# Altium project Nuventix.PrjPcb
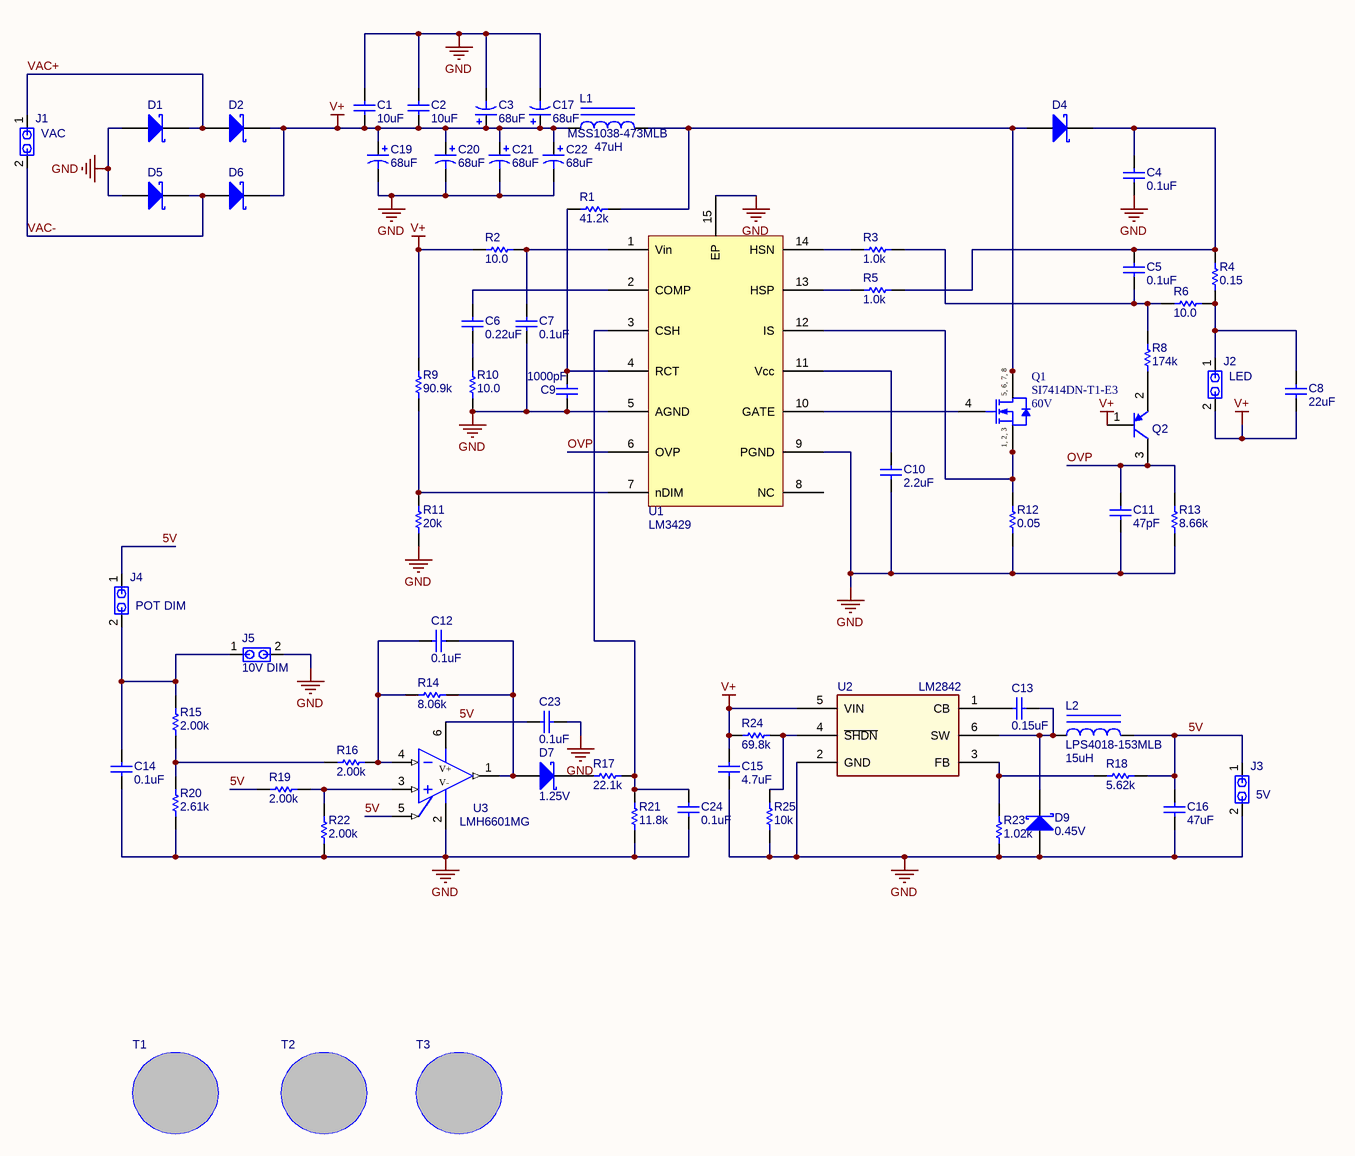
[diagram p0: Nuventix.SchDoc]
TechSupport: http://www.national.com/support; SCH_Rev: X1; PRJ_Title: Nuventix; PRJ_Customer: Public Release; PRJ_BasePN: xxxxxx; PCB_MinorRev: -001
1 sheet, 69 parts. Net scope: global (net labels, ports and power ports of the same name join across sheets).
Board file: Nuventix.PcbDoc

## Sheet Nuventix.SchDoc: LM3429 Nuventix Design
size B; Date: Not shown in title block; ApprovedBy: Not shown in title block; CheckedBy: Not shown in title block; Author: Not shown in title block; CompanyName: Not shown in title block; DrawnBy: Not shown in title block; Engineer: Not shown in title block; Organization: Not shown in title block; Address1: Not shown in title block; Address2: Not shown in title block; Address3: Not shown in title block; Address4: Not shown in title block; DocumentNumber: 1; Revision: Use project parameter SCH_Rev; SheetNumber: 1; SheetTotal: 1; PageSetup: Record=PageOptions|CenterHorizontal=True|CenterVertical=True|PrintScale=1.00|XCorrection=1.00|YCorrection=1.00|PrintKind=0|BorderSize=5000000|LeftOffset=0|BottomOffset=0|Orientation=2|PaperLength=1000|PaperWidth=1000|Scale=100|PaperSource=15|PrintQuality=600|MediaType=1|DitherType=10|PaperKind=Letter|PrintScaleMode=0

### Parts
C1  value 10uF  [2220]  (hidden comment: C5750X7R1H106M)
C2  value 10uF  [2220]  (hidden comment: C5750X7R1H106M)
C3  value 68uF  [7361-38]  (hidden comment: TPSV686M025R0095)
C4  value 0.1uF  [0805]  (hidden comment: 08053C104KAT2A)
C5  value 0.1uF  [0805]  (hidden comment: 08053C104KAT2A)
C6  value 0.22uF  [0603]  (hidden comment: 06033D224KAT2A)
C7  value 0.1uF  [0805]  (hidden comment: 08053C104KAT2A)
C8  value 22uF  [1210]  (hidden comment: GRM32ER61E226KE15L)
C9  value 1000pF  [0603]  (hidden comment: 06031C102JAT2A)
C10  value 2.2uF  [0805]  (hidden comment: 0805ZD225KAT2A)
C11  value 47pF  [0603]  (hidden comment: 06035A470JAT2A)
C12  value 0.1uF  [0805]  (hidden comment: GRM219R71C104KA01D)
C13  value 0.15uF  [0805]  (hidden comment: 08053C154KAT2A)
C14  value 0.1uF  [0805]  (hidden comment: GRM219R71C104KA01D)
C15  value 4.7uF  [1210]  (hidden comment: GRM32ER71H475KA88L)
C16  value 47uF  [0805]  (hidden comment: JMK212BJ476MG-T)
C17  value 68uF  [7361-38]  (hidden comment: TPSV686M025R0095)
C19  value 68uF  [7361-38]  (hidden comment: TPSV686M025R0095)
C20  value 68uF  [7361-38]  (hidden comment: TPSV686M025R0095)
C21  value 68uF  [7361-38]  (hidden comment: TPSV686M025R0095)
C22  value 68uF  [7361-38]  (hidden comment: TPSV686M025R0095)
C23  value 0.1uF  [0603]  (hidden comment: 0603YC104JAT2A)
C24  value 0.1uF  [0603]  (hidden comment: 0603YC104JAT2A)
D1  MBRA160T3G  [SMA]  (value not drawn)
D2  MBRA160T3G  [SMA]  (value not drawn)
D4  MBRA160T3G  [SMA]  (value not drawn)
D5  MBRA160T3G  [SMA]  (value not drawn)
D6  MBRA160T3G  [SMA]  (value not drawn)
D7  value 1.25V  [SOD-123]  (hidden comment: 1N4148W-7-F)
D9  value 0.45V  [SOD-123]  (hidden comment: 1N5819HW-7-F)
J1  VAC  [0.1" header 2-pos]
J2  LED  [0.1" header 2-pos]
J3  5V  [0.1" header 2-pos]
J4  POT DIM  [0.1" header 2-pos]
J5  10V DIM  [0.1" header 2-pos]
L1  value 47uH  [MSS1038]  (hidden comment: MSS1038-473MLB)
L2  LPS4018-153MLB  value 15uH  [LPS4018]
Q1  SI7414DN-T1-E3  value 60V  [1212-8 Powerpack_smask]
Q2  CMPT3906 LEAD FREE  [SOT-23]  (value not drawn)
R1  value 41.2k  [0603]  (hidden comment: CRCW060341k2FKEA)
R2  value 10.0  [0603]  (hidden comment: CRCW060310R0FKEA)
R3  value 1.0k  [0603]  (hidden comment: CRCW06031k00JNEA)
R4  value 0.15  [1206]  (hidden comment: ERJ-8RSJR15V)
R5  value 1.0k  [0603]  (hidden comment: CRCW06031k00JNEA)
R6  value 10.0  [0603]  (hidden comment: CRCW060310R0FKEA)
R8  value 174k  [0603]  (hidden comment: RT0603BRD07174KL)
R9  value 90.9k  [0603]  (hidden comment: CRCW060390k9FKEA)
R10  value 10.0  [0603]  (hidden comment: CRCW060310R0FKEA)
R11  value 20k  [0603]  (hidden comment: CRCW060320k0JNEA)
R12  value 0.05  [1206]  (hidden comment: LVK12R050FER)
R13  value 8.66k  [0603]  (hidden comment: CRCW06038k66FKEA)
R14  value 8.06k  [0603]  (hidden comment: CRCW06038k06FKEA)
R15  value 2.00k  [0603]  (hidden comment: CRCW06032k00FKEA)
R16  value 2.00k  [0603]  (hidden comment: CRCW06032k00FKEA)
R17  value 22.1k  [0603]  (hidden comment: CRCW060322k1FKEA)
R18  value 5.62k  [0603]  (hidden comment: CRCW06035k62FKEA)
R19  value 2.00k  [0603]  (hidden comment: CRCW06032k00FKEA)
R20  value 2.61k  [0603]  (hidden comment: CRCW06032k61FKEA)
R21  value 11.8k  [0603]  (hidden comment: CRCW060311k8FKEA)
R22  value 2.00k  [0603]  (hidden comment: CRCW06032k00FKEA)
R23  value 1.02k  [0603]  (hidden comment: CRCW06031k02FKEA)
R24  value 69.8k  [0603]  (hidden comment: CRCW060369k8FKEA)
R25  value 10k  [0603]  (hidden comment: CRCW060310k0JNEA)
T1  TOOLING HOLE  [4-40 Mounting Hole]  (value not drawn)  (no BOM)
T2  TOOLING HOLE  [4-40 Mounting Hole]  (value not drawn)  (no BOM)
T3  TOOLING HOLE  [4-40 Mounting Hole]  (value not drawn)  (no BOM)
U1  LM3429  [TSSOP-14_EP]
U2  LM2842  [MK06A]
U3  LMH6601MG  [MAA06A]

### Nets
GND: C1.2 C2.2 C3.2(-) C4.2 C7.2 C9.2 C10.2 C11.2 C14.2 C15.2 C16.2 C17.2(-) C19.2(-) C20.2(-) C21.2(-) C22.2(-) C23.2 C24.1 D1.1(A) D5.1(A) D9.1(A) J3.2 J5.2 R10.2 R11.2 R12.2 R13.2 R20.2 R21.2 R22.2 R23.1 R25.2 U1.5(AGND) U1.9(PGND) U1.15(EP) U2.2(GND) U3.2(V-)
V+: C1.1 C2.1 C3.1(+) C8.2 C15.1 C17.1(+) C19.1(+) C20.1(+) C21.1(+) C22.1(+) D2.2(K) D6.2(K) J2.2 L1.1 Q2.1(B) R2.2 R9.1 R24.2 U2.5(VIN)
5V: C16.1 C23.1 J3.1 J4.1 L2.2 R18.1 R19.2 U3.5(SD) U3.6(V+)
OVP: C11.1 Q2.3(C) R13.1 U1.6(OVP)
VAC+: D1.2(K) D2.1(A) J1.1
VAC-: D5.2(K) D6.1(A) J1.2
NetC4_1: C4.1 C5.1 D4.2(K) R4.1 R5.1
NetC5_2: C5.2 R3.1 R6.1 R8.1
NetC6_1: C6.1 U1.2(COMP)
NetC6_2: C6.2 R10.1
NetC7_1: C7.1 R2.1 U1.1(Vin)
NetC8_1: C8.1 J2.1 R4.2 R6.2
NetC9_1: C9.1 R1.1 U1.4(RCT)
NetC10_1: C10.1 U1.11(Vcc)
NetC12_1: C12.1 D7.1(A) R14.1 U3.1(OUT)
NetC12_2: C12.2 R14.2 R16.1 U3.4(IN-)
NetC13_1: C13.1 D9.2(K) L2.1 U2.6(SW)
NetC13_2: C13.2 U2.1(CB)
NetC14_1: C14.1 J4.2 J5.1 R15.1
NetC24_2: C24.2 R17.1 R21.1 U1.3(CSH)
NetD4_1: D4.1(A) L1.2 Q1.5(D) Q1.6(D) Q1.7(D) Q1.8(D) Q1.9(D) R1.2
NetD7_2: D7.2(K) R17.2
NetQ1_1: Q1.1(S) Q1.2(S) Q1.3(S) R12.1 U1.12(IS)
NetQ1_4: Q1.4(G) U1.10(GATE)
NetQ2_2: Q2.2(E) R8.2
NetR3_2: R3.2 U1.14(HSN)
NetR5_2: R5.2 U1.13(HSP)
NetR9_2: R9.2 R11.1 U1.7(nDIM)
NetR15_2: R15.2 R16.2 R20.1
NetR18_2: R18.2 R23.2 U2.3(FB)
NetR19_1: R19.1 R22.1 U3.3(IN+)
NetR24_1: R24.1 R25.1 U2.4(~{SHDN})

Not connected (* = marked no-connect by the designer): U1 8(NC)

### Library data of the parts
C1 C2 = C5750X7R1H106M: Ceramic, X7R, 50V, 20%; Manufacturer: TDK; ESR_Ohm: 0.003; IRMS_A: 5.5; Polarized: N; TaMax_C: 125; TaMin_C: -55; Tolerance_%: 20; VDC_V: 50; CompType: Capacitor; Cap_F: 10.0E-6; Value1: 0.003 Ohm
C3 C17 C19-C21 = TPSV686M025R0095: TA, 25V, 20%, 0.095 Ohm ESR; Manufacturer: AVX; Cap_Case: V; ESR_Ohm: 0.095; IRMS_A: 1.46; Polarized: Y; TaMax_C: 125; TaMin_C: -55; Tolerance_%: 20; VDC_V: 25; CompType: Capacitor; Cap_F: 68.0E-6; Dielectric: TPS
C4 C5 C7 = 08053C104KAT2A: Ceramic, X7R, 25V, 10%; Manufacturer: AVX; ESR_Ohm: 0.28; Polarized: N; TaMax_C: 125; TaMin_C: -55; Tolerance_%: 10; VDC_V: 25; Cap_F: 100.0E-9; CompType: Capacitor; Value1: 0.28 Ohm
C6 = 06033D224KAT2A: Ceramic, X5R, 25V, 10%; Manufacturer: AVX; ESR_Ohm: 0.036; Polarized: N; TaMax_C: 85; TaMin_C: -55; Tolerance_%: 10; VDC_V: 25; Cap_F: 220.0E-9; CompType: Capacitor; Value1: 0.036 Ohm
C8 = GRM32ER61E226KE15L: Ceramic, X5R, 25V, 10%; Manufacturer: MuRata; ESR_Ohm: 0.002; Polarized: N; TaMax_C: 85; TaMin_C: -55; Tolerance_%: 10; VDC_V: 25; Cap_F: 22.0E-6; CompType: Capacitor; Value1: 0.002 Ohm
C9 = 06031C102JAT2A: Ceramic, X7R, 100V, 5%; Manufacturer: AVX; ESR_Ohm: 0.276; Polarized: N; TaMax_C: 125; TaMin_C: -55; Tolerance_%: 5; VDC_V: 100; Cap_F: 1.0E-9; CompType: Capacitor; Value1: 0.276 Ohm
C10 = 0805ZD225KAT2A: Ceramic, X5R, 10V, 10%; Manufacturer: AVX; ESR_Ohm: 0.009; Polarized: N; TaMax_C: 85; TaMin_C: -55; Tolerance_%: 10; Cap_F: 2.2E-6; CompType: Capacitor; Value1: 0.009 Ohm
C11 = 06035A470JAT2A: Ceramic, C0G/NP0, 50V, 5%; Manufacturer: AVX; ESR_Ohm: 0.174; Polarized: N; TaMax_C: 125; TaMin_C: -55; Tolerance_%: 5; VDC_V: 50; Cap_F: 47.0E-12; CompType: Capacitor; Value1: 0.174 Ohm
C12 C14 = GRM219R71C104KA01D: Ceramic, X7R, 16V, 10%; Manufacturer: MuRata; Polarized: N; TaMax_C: 125; TaMin_C: -55; Tolerance_%: 10; VDC_V: 16; Cap_F: 100.0E-9; CompType: Capacitor
C13 = 08053C154KAT2A: Ceramic, X7R, 25V, 10%; Manufacturer: AVX; ESR_Ohm: 0.02; Polarized: N; TaMax_C: 125; TaMin_C: -55; Tolerance_%: 10; VDC_V: 25; Cap_F: 150.0E-9; CompType: Capacitor; Value1: 0.02 Ohm
C15 = GRM32ER71H475KA88L: Ceramic, X7R, 50V, 10%; Manufacturer: MuRata; ESR_Ohm: 0.002; Polarized: N; TaMax_C: 125; TaMin_C: -55; Tolerance_%: 10; VDC_V: 50; Cap_F: 4.7E-6; CompType: Capacitor; Value1: 0.002 Ohm
C16 = JMK212BJ476MG-T: Ceramic, X5R, 6.3V, 20%; Manufacturer: Taiyo Yuden; Polarized: N; TaMax_C: 85; TaMin_C: -55; Tolerance_%: 20; VDC_V: 6.3; Cap_F: 47.0E-6; CompType: Capacitor
C22 = TPSV686M025R0095: TA, 25V, 20%, 0.095 Ohm ESR; Manufacturer: AVX; Cap_Case: V; ESR_Ohm: 0.095; IRMS_A: 1.46; Polarized: Y; TaMax_C: 125; TaMin_C: -55; Tolerance_%: 20; VDC_V: 25; Cap_F: 68.0E-6; CompType: Capacitor; Dielectric: TPS
C23 C24 = 0603YC104JAT2A: Ceramic, X7R, 16V, 5%; Manufacturer: AVX; ESR_Ohm: 0.039; Polarized: N; TaMax_C: 125; TaMin_C: -55; Tolerance_%: 5; VDC_V: 16; Cap_F: 100.0E-9; CompType: Capacitor; Value1: 0.039 Ohm
D1 D2 D4-D6 = MBRA160T3G: Vr = 60V, Io = 1A, Vf = 0.51V; Manufacturer: ON Semiconductor; RJC_CperW: 35; Vf_V: 0.51; Io_A: 1; Vr_V: 60; TJMax_C: 150; Type: Schottky; CompType: Diode
D7 = 1N4148W-7-F: Vr = 100V, Io = 0.15A, Vf = 1.25V; Manufacturer: Diodes Inc.; Vf_V: 1.25; Io_A: 0.15; Vr_V: 100; TJMax_C: 150; Type: Ultrafast; CompType: Diode
D9 = 1N5819HW-7-F: Vr = 40V, Io = 1A, Vf = 0.45V; Manufacturer: Diodes Inc.; Vf_V: 0.45; Io_A: 1; Vr_V: 40; TJMax_C: 125; Type: Schottky; CompType: Diode
J1-J5 = CONN 1X2: Header, TH, 100mil spacing; Manufacturer: Molex; Value: 1x2
L1 = MSS1038-473MLB: Shielded Drum Core, 2.25A, 0.112 Ohm; Manufacturer: Coilcraft Inc.; CompType: Inductor; Ind_H: 47.0E-6; DCR_Ohm: 0.112; Imax_A: 2.25; Material: Ferrite
L2 = LPS4018-153MLB: Shielded Drum Core, 0.94A, 0.26 Ohm; Manufacturer: Coilcraft Inc.; CompType: Inductor; Ind_H: 15.0E-6; DCR_Ohm: 0.26; Imax_A: 0.94; Material: Ferrite
Q1 = SI7414DN-T1-E3: 5.6A, 16nC, rDS(on) @ 4.5V =0.036 Ohm; Manufacturer: Vishay-Siliconix; CompType: MOSFET; ChType: N; VdsMax_V: 60; Rdson45_Ohm: 0.036; QgTyp_nC: 16; Vgs_V: 20; IdsMax_A: 5.6
Q2 = CMPT3906 LEAD FREE: PNP, 0.2A, 40V; Manufacturer: Central Semiconductor; CompType: BJT; PNP: 1; NPN: 0; Vceo_V: 40; Vcesat1_V: 0.25; Value: 0.25V; IcRated_A: 0.2
R1 = CRCW060341k2FKEA: 1%, 0.1W; Manufacturer: Vishay-Dale; CompType: Resistor; Tolerance_%: 1; VDC_V: 75; Power_W: 0.1; Res_Ohm: 41200; Value_Code: 41k2; EIA_Code: E96
R2 R6 R10 = CRCW060310R0FKEA: 1%, 0.1W; Manufacturer: Vishay-Dale; CompType: Resistor; Tolerance_%: 1; VDC_V: 75; Power_W: 0.1; Res_Ohm: 10; Value_Code: 10R0; EIA_Code: E96
R3 R5 = CRCW06031k00JNEA: 5%, 0.1W; Manufacturer: Vishay-Dale; CompType: Resistor; Tolerance_%: 5; VDC_V: 75; Power_W: 0.1; Res_Ohm: 1000; Value_Code: 1k00; EIA_Code: E24
R4 = ERJ-8RSJR15V: 5%, 0.25W; Manufacturer: Panasonic; CompType: Resistor; Tolerance_%: 5; Power_W: 0.25; Value_Code: R150; EIA_Code: E24
R8 = RT0603BRD07174KL: 0.1%, 0.1W; Manufacturer: Yageo America; CompType: Resistor; Tolerance_%: 0.1; VDC_V: 75; Res_Ohm: 174000; EIA_Code: E192
R9 = CRCW060390k9FKEA: 1%, 0.1W; Manufacturer: Vishay-Dale; CompType: Resistor; Tolerance_%: 1; VDC_V: 75; Power_W: 0.1; Res_Ohm: 90900; Value_Code: 90k9; EIA_Code: E96
R11 = CRCW060320k0JNEA: 5%, 0.1W; Manufacturer: Vishay-Dale; CompType: Resistor; Tolerance_%: 5; VDC_V: 75; Power_W: 0.1; Res_Ohm: 20000; Value_Code: 20k0; EIA_Code: E24
R12 = LVK12R050FER: 1%, 0.5W; Manufacturer: Ohmite; CompType: Resistor; Tolerance_%: 1; Power_W: 0.5; Value_Code: R050; EIA_Code: E96
R13 = CRCW06038k66FKEA: 1%, 0.1W; Manufacturer: Vishay-Dale; CompType: Resistor; Tolerance_%: 1; VDC_V: 75; Power_W: 0.1; Res_Ohm: 8660; Value_Code: 8k66; EIA_Code: E96
R14 = CRCW06038k06FKEA: 1%, 0.1W; Manufacturer: Vishay-Dale; CompType: Resistor; Tolerance_%: 1; VDC_V: 75; Power_W: 0.1; Res_Ohm: 8060; Value_Code: 8k06; EIA_Code: E96
R15 R16 R19 R22 = CRCW06032k00FKEA: 1%, 0.1W; Manufacturer: Vishay-Dale; CompType: Resistor; Tolerance_%: 1; VDC_V: 75; Power_W: 0.1; Res_Ohm: 2000; Value_Code: 2k00; EIA_Code: E96
R17 = CRCW060322k1FKEA: 1%, 0.1W; Manufacturer: Vishay-Dale; CompType: Resistor; Tolerance_%: 1; VDC_V: 75; Power_W: 0.1; Res_Ohm: 22100; Value_Code: 22k1; EIA_Code: E96
R18 = CRCW06035k62FKEA: 1%, 0.1W; Manufacturer: Vishay-Dale; CompType: Resistor; Tolerance_%: 1; VDC_V: 75; Power_W: 0.1; Res_Ohm: 5620; Value_Code: 5k62; EIA_Code: E96
R20 = CRCW06032k61FKEA: 1%, 0.1W; Manufacturer: Vishay-Dale; CompType: Resistor; Tolerance_%: 1; VDC_V: 75; Power_W: 0.1; Res_Ohm: 2610; Value_Code: 2k61; EIA_Code: E96
R21 = CRCW060311k8FKEA: 1%, 0.1W; Manufacturer: Vishay-Dale; CompType: Resistor; Tolerance_%: 1; VDC_V: 75; Power_W: 0.1; Res_Ohm: 11800; Value_Code: 11k8; EIA_Code: E96
R23 = CRCW06031k02FKEA: 1%, 0.1W; Manufacturer: Vishay-Dale; CompType: Resistor; Tolerance_%: 1; VDC_V: 75; Power_W: 0.1; Res_Ohm: 1020; Value_Code: 1k02; EIA_Code: E96
R24 = CRCW060369k8FKEA: 1%, 0.1W; Manufacturer: Vishay-Dale; CompType: Resistor; Tolerance_%: 1; VDC_V: 75; Power_W: 0.1; Res_Ohm: 69800; Value_Code: 69k8; EIA_Code: E96
R25 = CRCW060310k0JNEA: 5%, 0.1W; Manufacturer: Vishay-Dale; CompType: Resistor; Tolerance_%: 5; VDC_V: 75; Power_W: 0.1; Res_Ohm: 10000; Value_Code: 10k0; EIA_Code: E24
U1 = LM3429: N-Channel Controller for Constant Current LED Drivers; Manufacturer: National Semiconductor; PartNumber: LM3429MH
U2 = LM284X_0: 300 mA/600 mA up to 42V Input Step-Down DC/DC Regulator in Thin SOT-23; Manufacturer: National Semiconductor; PartNumber: LM2842XMK-ADJL
U3 = LMH6601MG: 2.4V R-R Out CMOS Video OpAmp with Shutdown; Manufacturer: National Semiconductor; CompType: OpAmp IC; TaMin_C: -40.0; TaMax_C: 85.0; Sim Note: Shutdown not modeled

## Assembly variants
-100A: not fitted C3 C17 C19 C20 C21 C22 D1 D6; alternate parts D2 -> CRCW12060000Z0EA, D5 -> CRCW12060000Z0EA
